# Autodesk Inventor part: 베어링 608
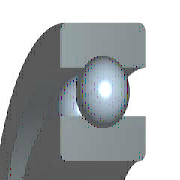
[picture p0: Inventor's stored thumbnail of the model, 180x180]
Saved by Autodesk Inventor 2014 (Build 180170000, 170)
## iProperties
IsCustomPart: 1
Created: 2012-02
Part Number: 베어링 608
Material: 강철, 연강
Description: 깊은 그루브 볼 베어링
Document SubType Name: Modeling
Standard: KS B 2023
Designer: mduedu
Standards Organization: KS
Language: ko-KR
Size Designation: 608 - 8 x 22 x 7
Categories: <MemberInstance><Categories><Category DisplayName="샤프트 부품" InternalName="7f7aeb1f-a693-4053-b835-cee3144e0d98" Mnemonic="SHFT"><Category DisplayName="베어링" Inter
Density: 7.86 g/cm^3
Mass: 10.9696 g
Surface Area: 20.0754 cm^2
Volume: 1.39562 cm^3
Appearance: 주황색
Author: mduedu
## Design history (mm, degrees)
sketch "스케치" dims "d0" = 3.64 (= -0.26 x WD + 0.26 x BD)
  geometry: L1 (1.68, 7.5)-(5.32, 7.5); L2 (3.5, 7.5)-(3.5, 5.68); L3 (3.5, 7.5)-(3.5, 9.32); L4 (2.148, 6.282)-(0, 6.282); L5 (0, 4)-(7, 4); L6 (2.148, 8.718)-(0, 8.718); L7 (0, 11)-(7, 11); L8 (7, 4)-(7, 6.282); L9 (4.852, 6.282)-(7, 6.282); L10 (4.852, 8.718)-(7, 8.718); L11 (7, 11)-(7, 8.718); L12 (-1.4, 0)-(8.4, 0) reference; L13 (0, -0.3)-(0, 5.3) reference
  constraints: 22 end point, 4 point on line, 2 collinear, 2 perpendicular, 2 symmetric about line, 1 midpoint, 1 parallel, 14 other
  dimensions: "d9" = 8 diameter of L5 L12 (= WD); "d11" = 22 diameter of L7 L12 (= BD); "d12" = 7 distance between parallel lines of L8 L13 (= KB); "d13" = 12.564 diameter of L9 L12 (= 0.326 x BD + 0.674 x WD)
revolve "본체" stored, may be unused: angle "d6" = 90 deg
revolve "볼" stored, may be unused: angle "d7" = 90 deg
pattern_circular "IDS_ARRAYBALL[SIMPL:T]" dims angle "d3" = 360 deg
body "Solid1"
fillet "모깎기1" dims "d1" = 0.3 (= KRS)
other parameters: "WD" = 8 [user parameter; used in 5 equation terms], "BD" = 22 [user parameter; used in 5 equation terms], "KB" = 7 [user parameter; used in 1 equation term], "KRS" = 0.3 [user parameter; used in 1 equation term], "d4" = 0, "d5" = 0, "d8" = 0, "d14" = 0, "d15" = 0, "BBA" = 0 [user parameter], "BC0" = 1370000 [user parameter], "BC" = 3250000 [user parameter], "BR" = 11 (= 0.5 x BD) [user parameter], "WR" = 4 (= 0.5 x WD) [user parameter]
